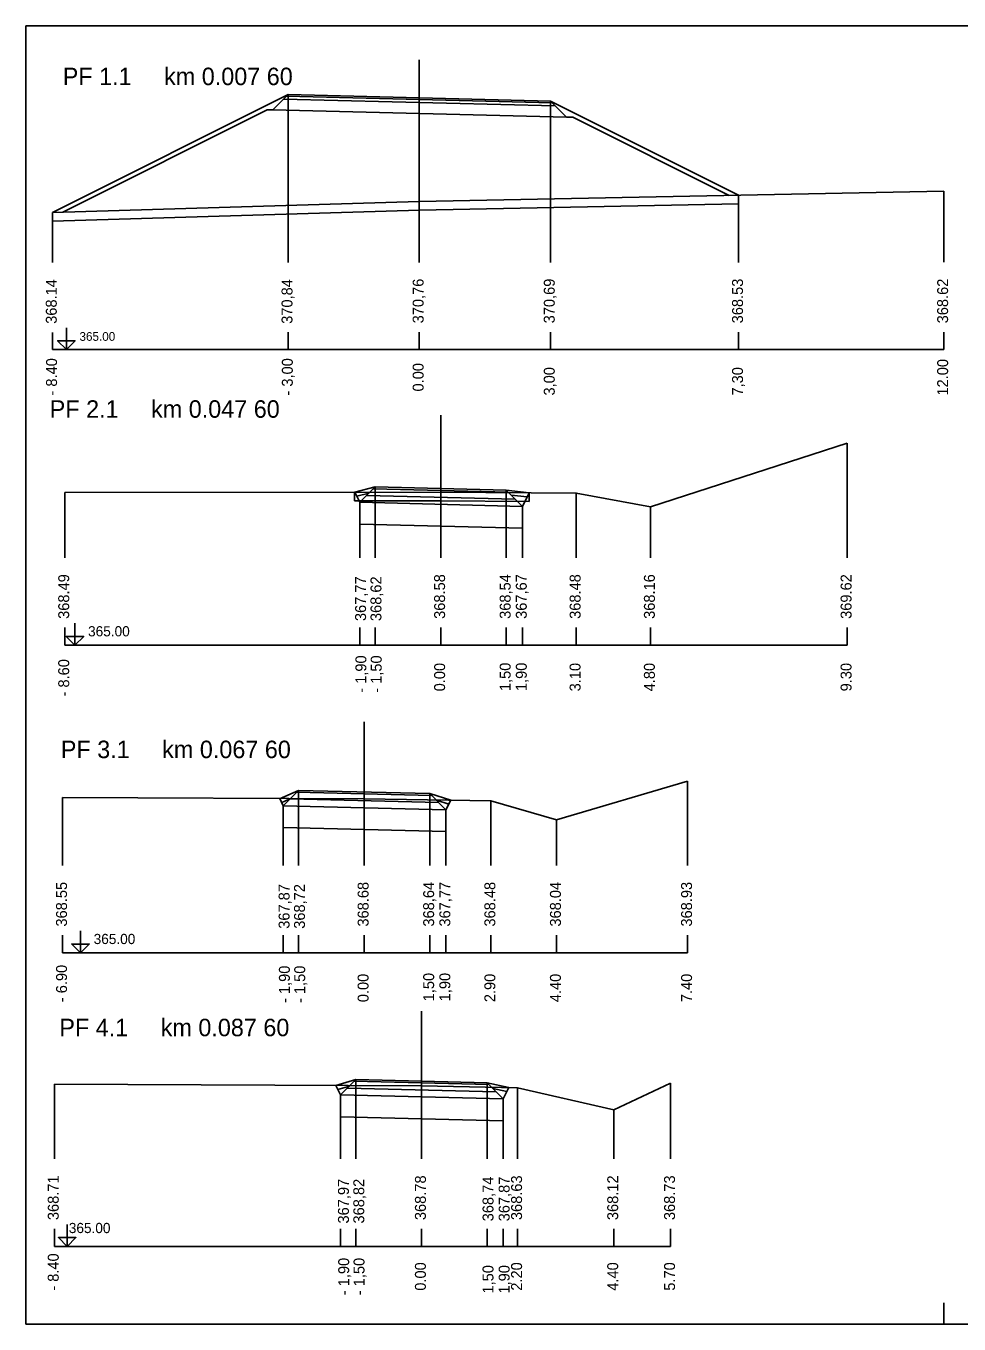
# Model space of a CAD drawing. Extents: x 82.5 to 124.5, y 182.2 to 211.9.
# Drawn here: x 82.54 to 103.89, y 182.15 to 211.85 of the extents above; entities that cross this region are included whole.
import ezdxf

# ---------------------------------------------------------------- set-up
doc = ezdxf.new("R2010")
doc.units = 0
for name, color, linetype in [('Level 1-1', 7, 'Continuous'), ('NKOD', 7, 'Continuous'), ('NPOP', 7, 'Continuous'), ('NTVA', 7, 'Continuous')]:
    doc.layers.add(name, color=color, linetype=linetype)

msp = doc.modelspace()

# ---------------------------------------------------------------- linework, layer by layer
at = {"layer": 'Level 1-1'}
for p, q in [((82.539, 182.151), (82.539, 211.851)), ((88.537, 210.282), (83.144, 207.586)), ((88.537, 210.282), (88.186, 209.931)), ((94.537, 210.132), (88.537, 210.282)), ((88.537, 206.436), (88.537, 210.282)), ((94.65, 210.02), (88.43, 210.175)), ((94.578, 210.091), (88.498, 210.243)), ((94.537, 210.132), (98.844, 207.979)), ((94.537, 210.132), (94.906, 209.763)), ((94.537, 206.436), (94.537, 210.132)), ((88.058, 209.931), (83.381, 207.593)), ((88.186, 209.931), (88.058, 209.931)), ((94.906, 209.763), (88.186, 209.931)), ((94.906, 209.763), (95.052, 209.763)), ((95.052, 209.763), (98.628, 207.975)), ((98.844, 207.979), (98.844, 207.779)), ((98.844, 206.436), (98.844, 207.979)), ((83.144, 207.586), (83.144, 207.386)), ((88.537, 204.447), (88.537, 204.847)), ((94.537, 204.447), (94.537, 204.847)), ((98.844, 204.447), (98.844, 204.847)), ((90.059, 201.19), (90.059, 200.983)), ((90.061, 201.183), (90.528, 201.303)), ((90.177, 200.952), (90.061, 201.183)), ((90.107, 201.092), (90.389, 201.164)), ((90.528, 201.303), (90.177, 200.952)), ((93.733, 201.023), (90.333, 201.108)), ((93.569, 201.187), (90.489, 201.264)), ((93.528, 201.228), (90.528, 201.303)), ((90.528, 199.685), (90.528, 201.303)), ((93.528, 201.228), (93.897, 200.859)), ((93.528, 201.228), (94.054, 201.172)), ((93.528, 199.685), (93.528, 201.228)), ((93.641, 201.115), (94.006, 201.077)), ((93.897, 200.859), (94.054, 201.172)), ((94.054, 201.172), (94.054, 200.972)), ((93.897, 200.859), (90.177, 200.952)), ((90.177, 200.952), (90.177, 200.452)), ((93.897, 200.859), (93.897, 200.359)), ((93.897, 200.359), (90.177, 200.452)), ((90.177, 199.685), (90.177, 200.452)), ((93.897, 199.685), (93.897, 200.359)), ((90.177, 197.685), (90.177, 198.085)), ((90.528, 197.685), (90.528, 198.085)), ((93.528, 197.685), (93.528, 198.085)), ((93.897, 197.685), (93.897, 198.085)), ((88.341, 194.167), (88.778, 194.362)), ((88.778, 194.362), (88.427, 194.011)), ((91.819, 194.246), (88.739, 194.323)), ((91.778, 194.287), (88.778, 194.362)), ((88.778, 192.645), (88.778, 194.362)), ((91.778, 194.287), (92.148, 193.918)), ((91.778, 194.287), (92.257, 194.138)), ((91.778, 192.645), (91.778, 194.287)), ((88.427, 194.011), (88.346, 194.173)), ((88.382, 194.076), (88.58, 194.165)), ((92.148, 193.918), (88.427, 194.011)), ((88.427, 194.011), (88.427, 193.511)), ((91.983, 194.082), (88.583, 194.167)), ((91.931, 194.135), (92.212, 194.047)), ((92.148, 193.918), (92.257, 194.138)), ((92.148, 193.918), (92.148, 193.418)), ((92.148, 193.418), (88.427, 193.511)), ((88.427, 192.645), (88.427, 193.511)), ((92.148, 192.645), (92.148, 193.418)), ((88.427, 190.645), (88.427, 191.045)), ((88.778, 190.645), (88.778, 191.045)), ((91.778, 190.645), (91.778, 191.045)), ((92.148, 190.645), (92.148, 191.045)), ((89.631, 187.608), (90.089, 187.746)), ((90.089, 187.746), (89.738, 187.395)), ((93.13, 187.63), (90.05, 187.707)), ((93.089, 187.671), (90.089, 187.746)), ((90.089, 185.929), (90.089, 187.746)), ((89.738, 187.395), (89.631, 187.608)), ((89.676, 187.518), (89.939, 187.597)), ((93.294, 187.466), (89.894, 187.551)), ((93.089, 187.671), (93.458, 187.302)), ((93.089, 187.671), (93.588, 187.563)), ((93.089, 185.929), (93.089, 187.671)), ((93.22, 187.541), (93.542, 187.47)), ((93.458, 187.302), (93.588, 187.563)), ((93.458, 187.302), (89.738, 187.395)), ((89.738, 187.395), (89.738, 186.895)), ((93.458, 187.302), (93.458, 186.802)), ((93.458, 186.802), (89.738, 186.895)), ((89.738, 185.929), (89.738, 186.895)), ((93.458, 185.929), (93.458, 186.802)), ((89.738, 183.929), (89.738, 184.329)), ((90.089, 183.929), (90.089, 184.329)), ((93.089, 183.929), (93.089, 184.329)), ((93.458, 183.929), (93.458, 184.329)), ((103.539, 182.151), (103.539, 182.637))]:
    msp.add_line(p, q, dxfattribs=at)
msp.add_lwpolyline([(82.539, 211.851), (124.539, 211.851), (124.539, 182.151), (82.539, 182.151)], close=True, dxfattribs=at)
for points in [[(98.844, 207.779), (91.542, 207.638), (83.144, 207.386)], [(94.054, 200.972), (92.028, 200.985), (90.059, 200.983)]]:
    msp.add_lwpolyline(points, dxfattribs=at)
at = {"layer": 'NKOD'}
for p, q in [((91.537, 206.436), (91.537, 211.073)), ((103.537, 206.447), (103.537, 208.07)), ((83.144, 206.436), (83.144, 207.586)), ((83.144, 204.447), (83.144, 204.836)), ((91.537, 204.447), (91.537, 204.847)), ((103.537, 204.447), (103.537, 204.847)), ((103.537, 204.447), (83.144, 204.447)), ((92.028, 199.685), (92.028, 202.947)), ((101.328, 199.685), (101.328, 202.305)), ((83.428, 199.685), (83.428, 201.175)), ((95.128, 199.685), (95.128, 201.165)), ((96.828, 199.685), (96.828, 200.845)), ((83.428, 197.685), (83.428, 198.085)), ((92.028, 197.685), (92.028, 198.085)), ((95.128, 197.685), (95.128, 198.085)), ((96.828, 197.685), (96.828, 198.085)), ((101.328, 197.685), (101.328, 198.085)), ((101.328, 197.685), (83.428, 197.685)), ((90.278, 192.645), (90.278, 195.926)), ((97.678, 192.645), (97.678, 194.575)), ((83.378, 192.645), (83.378, 194.195)), ((93.178, 192.645), (93.178, 194.125)), ((94.678, 192.645), (94.678, 193.685)), ((83.378, 190.645), (83.378, 191.045)), ((90.278, 190.645), (90.278, 191.045)), ((93.178, 190.645), (93.178, 191.045)), ((94.678, 190.645), (94.678, 191.045)), ((97.678, 190.645), (97.678, 191.045)), ((97.678, 190.645), (83.378, 190.645)), ((91.589, 185.929), (91.589, 189.31)), ((83.189, 185.929), (83.189, 187.639)), ((93.789, 185.929), (93.789, 187.559)), ((97.289, 185.929), (97.289, 187.659)), ((95.989, 185.929), (95.989, 187.049)), ((83.189, 183.929), (83.189, 184.329)), ((91.589, 183.929), (91.589, 184.329)), ((93.789, 183.929), (93.789, 184.329)), ((95.989, 183.929), (95.989, 184.329)), ((97.289, 183.929), (97.289, 184.329)), ((97.289, 183.929), (83.189, 183.929))]:
    msp.add_line(p, q, dxfattribs=at)
for points in [[(83.464, 204.947), (83.464, 204.447), (83.264, 204.647), (83.664, 204.647), (83.464, 204.447)], [(83.661, 198.185), (83.661, 197.685), (83.461, 197.885), (83.861, 197.885), (83.661, 197.685)], [(83.788, 191.145), (83.788, 190.645), (83.588, 190.845), (83.988, 190.845), (83.788, 190.645)], [(83.483, 184.429), (83.483, 183.929), (83.283, 184.129), (83.683, 184.129), (83.483, 183.929)]]:
    msp.add_lwpolyline(points, dxfattribs=at)
at = {"layer": 'NTVA'}
for p, q in [((91.589, 187.599), (83.189, 187.639)), ((93.789, 187.559), (91.589, 187.599)), ((95.989, 187.049), (93.789, 187.559)), ((97.289, 187.659), (95.989, 187.049))]:
    msp.add_line(p, q, dxfattribs=at)
for points in [[(103.537, 208.07), (91.537, 207.837), (83.144, 207.586)], [(101.328, 202.305), (96.828, 200.845), (95.128, 201.165), (92.028, 201.185), (83.428, 201.175)], [(97.678, 194.575), (94.678, 193.685), (93.178, 194.125), (90.278, 194.165), (83.378, 194.195)]]:
    msp.add_lwpolyline(points, dxfattribs=at)

# ---------------------------------------------------------------- texts
at = {"layer": 'NKOD'}
for s, p in [('368.14', (83.244, 205.036)), ('370,84', (88.637, 205.036)), ('370,76', (91.637, 205.047)), ('370,69 ', (94.637, 205.047)), ('368.53', (98.944, 205.047)), ('368.62 ', (103.637, 205.047)), (' - 8.40 ', (83.25, 203.302)), (' - 3,00', (88.644, 203.302)), ('  0.00 ', (91.637, 203.302)), (' 12.00 ', (103.637, 203.302)), (' 3,00', (94.637, 203.302)), (' 7,30', (98.944, 203.302)), ('368.49 ', (83.528, 198.285)), ('368.58', (92.128, 198.285)), ('368,54', (93.628, 198.285)), ('367,67', (93.997, 198.285)), ('368.48 ', (95.228, 198.285)), ('368.16 ', (96.928, 198.285)), ('369.62 ', (101.428, 198.285)), ('367,77', (90.32, 198.235)), ('368,62', (90.672, 198.235)), ('  - 8.60 ', (83.528, 196.324)), (' - 1,90', (90.327, 196.502)), (' - 1,50', (90.678, 196.502)), ('  0.00 ', (92.128, 196.441)), (' 1,50', (93.628, 196.54)), (' 1,90', (93.997, 196.54)), ('  3.10 ', (95.228, 196.441)), ('  4.80 ', (96.928, 196.441)), ('  9.30 ', (101.428, 196.441)), ('368.55 ', (83.478, 191.245)), ('367,87', (88.57, 191.195)), ('368,72', (88.922, 191.195)), ('368.68', (90.378, 191.245)), ('368,64', (91.878, 191.245)), ('367,77', (92.248, 191.245)), ('368.48 ', (93.278, 191.245)), ('368.04 ', (94.778, 191.245)), ('368.93 ', (97.778, 191.245)), ('  - 6.90 ', (83.478, 189.329)), (' - 1,90', (88.577, 189.404)), (' - 1,50', (88.928, 189.404)), ('  0.00 ', (90.378, 189.329)), (' 1,50', (91.878, 189.442)), (' 1,90', (92.248, 189.442)), ('  2.90 ', (93.278, 189.329)), ('  4.40 ', (94.778, 189.329)), ('  7.40 ', (97.778, 189.329)), ('368.71 ', (83.289, 184.529)), ('367,97', (89.928, 184.451)), ('368,82', (90.279, 184.451)), ('368.78', (91.689, 184.529)), ('368,74', (93.236, 184.501)), ('367,87', (93.605, 184.501)), ('368.63 ', (93.889, 184.529)), ('368.12 ', (96.089, 184.529)), ('368.73 ', (97.389, 184.529)), ('  - 8.40 ', (83.289, 182.728)), (' - 1,90', (89.934, 182.718)), (' - 1,50', (90.285, 182.718)), ('  0.00 ', (91.689, 182.728)), ('  2.20 ', (93.889, 182.728)), ('  4.40 ', (96.089, 182.728)), ('  5.70 ', (97.389, 182.728)), (' 1,50', (93.236, 182.756)), (' 1,90', (93.605, 182.756))]:
    msp.add_text(s, height=0.25, rotation=90, dxfattribs=at).set_placement(p)
for height, p in [(0.2, (83.764, 204.647)), (0.233, (83.961, 197.885)), (0.233, (84.088, 190.845)), (0.233, (83.52, 184.232))]:
    msp.add_text('365.00', height=height, dxfattribs=at).set_placement(p)
at = {"layer": 'NPOP'}
for s, p in [('PF 1.1     km 0.007 60', (83.381, 210.497)), ('PF 2.1     km 0.047 60', (83.083, 202.887)), ('PF 3.1     km 0.067 60', (83.337, 195.099)), ('PF 4.1     km 0.087 60', (83.303, 188.736))]:
    msp.add_text(s, height=0.4, dxfattribs=at).set_placement(p)

doc.saveas('drawing.dxf')
